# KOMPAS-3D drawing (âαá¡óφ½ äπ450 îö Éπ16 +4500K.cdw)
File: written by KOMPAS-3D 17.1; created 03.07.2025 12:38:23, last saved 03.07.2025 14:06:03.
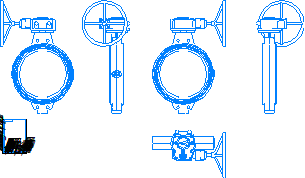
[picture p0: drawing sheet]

Sheet 1: A4, portrait

Title block, sheet 1: sheets: 1; sheet format: A4; stored path: \\adlc.lan\data\АДЛ_ПКД\3D-модели\ADL production\Дисковые поворотные затворы ГРАНВЭЛ\межфланцевый с китайским редуктором Ру16\KOMPAS 2D\Гранвэл Ду450 МФ Ру16 +4500K.cdw

Views: Вид 1, Спереди, Проекционный вид 2, Проекционный вид 3, Проекционный вид 4, Проекционный вид 5
Referenced files in \\adlc.lan\data\АДЛ_ПКД\3D-модели\ADL production\Дисковые поворотные затворы ГРАНВЭЛ\межфланцевый с китайским редуктором Ру16\KOMPAS 3D\: Гранвэл Ду450 МФ Ру16 +4500K.m3d
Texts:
  Andrey
  АДЛ
Dimensions and other numbers on the sheet: 1:1; 1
